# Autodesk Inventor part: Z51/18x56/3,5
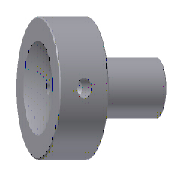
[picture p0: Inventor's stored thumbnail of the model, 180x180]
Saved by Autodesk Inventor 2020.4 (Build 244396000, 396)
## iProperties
Created: 2019-01
Part Number: Z51/18x56/3,5
Material: 1.2826
Description: Buse d'injection
Document SubType Name: Modeling
Designer: mel
Standard Revision: 1
Manufacturer: HASCO
Language: fr-FR
Size Designation: 18x56/3,5
Categories: <MemberInstance><Categories><Category DisplayName="Moule" InternalName="349578f2-f4d4-4954-8c09-8e99297a61c0" Mnemonic="MOLD"><Category DisplayName="Canal d'inj
Density: 7.82 g/cm^3
Appearance: Par défaut
Mass: 449.949 g
Surface Area: 98.7904 cm^2
Volume: 57.5383 cm^3
IsCustomPart: 1
Author: mel
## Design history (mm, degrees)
workplane "Work Plane1"
sketch "Sketch4"
  geometry: L1 (0, -98.4)-(0, 58.4) reference; L2 (0, 36)-(19.5, 36); L3 (19.5, 36)-(19.5, 0); L4 (9, -56)-(0, -56); L5 (0, -56)-(0, 36); L6 (9, -3)-(9, -56); L7 (12, 0)-(19.5, 0); L8 (12, 0)-(9, -3); 2 further points
  constraints: 14 end point, 4 point on line, 2 horizontal, 2 parallel, 1 perpendicular, 1 vertical
  dimensions: "d56" = 3 distance of L7.start point (9, 0) (= R3_CS); "d57" = 3 distance of L6.start point (9, 0) (= d56); "d58" = 39 diameter of L3 L1 (= d1_CS); "d59" = 36 distance between parallel lines of L7 L2 (= K_CS); "d60" = 18 diameter of L6 L1 (= D_CS); "d61" = 56 distance between parallel lines of L7 L4 (= L_CS)
feature "RévolutionSrf1" sketch "Sketch4" dims angle "d33" = 90 deg
feature "Sculpter4"
body "Solid1"
revolve "Révolution1" stored, may be unused: angle "d10" = 90 deg
revolve "Révolution2" stored, may be unused: angle "d13" = 90 deg
sketch "Sketch3"
  geometry: 2 further points
  constraints: 1 vertical alignment
  dimensions: "d43" = 9 distance of point (0, -9) point (0, 0) (= 0.5 x K_)
hole "Perçage1" sketch "Sketch3" diameter "d15" = 4 (= pd1); stored, may be unused: countersink angle "d19" = 90 deg, drill point angle "d21" = 118 deg; dims "d16" = 6, "d17" = 4, "d18" = 2, "d20" = 6 (= pl1)
chamfer "Chanfrein1" distance "d22" = 0.3; stored, may be unused: second distance "d23" = 2, angle "d24" = 45 deg
sketch "Sketch1"
  geometry: L1 (0, -94.8)-(0, 36.8) reference; L2 (1.75, 18)-(19, 18); L3 (19, 18)-(19, 0); L4 (19, 0)-(12, 0); L5 (9, -3)-(9, -56); L6 (9, -56)-(3.688, -56); L7 (3.688, -56)-(1.75, 18); A1 r 3 centre (12, -3) between (12, 0) and (9, -3); 2 further points
  constraints: 12 end point, 3 parallel, 2 perpendicular, 2 point on circle, 2 point on line, 2 tangent, 1 centre point
  dimensions: "d0" = 18 diameter of L5 L1 (= D); "d3" = 38 diameter of L3 L1 (= d1); "d6" = 1.5 deg angle of L7 L1 (= 0.5 x Taper); "d7" = 18 distance between parallel lines of L4 L2 (= K_); "d8" = 56 distance between parallel lines of L4 L6 (= L); "d9" = 3 radius of A1 (= R3); "d62" = 3.5 diameter of point (1.75, 18) L1 (= d_); "d63" = 0 distance from line of point (1.75, 18) L2 (computed from Rd)
sketch "Sketch2"
  geometry: L1 (0, -100.98)-(0, 73.881) reference; L2 (3.688, -56)-(1.75, 18) reference; L3 (-19, 18)-(19, 18) reference; L4 (0, 48.901)-(0, 17.901); A1 r 15.5 centre (0, 33.401) between (0, 17.901) and (0, 48.901); 2 further points
  constraints: 3 point on circle, 3 point on line, 2 end point, 1 centre point, 1 midpoint
  dimensions: "d64" = 0 distance from line of point (1.75, 18) L3 (computed from Rd); "d67" = 15.5 radius of A1 (= Rk)
body "Srf1"
feature "Surface2"
body "Srf3"
other parameters: "L" = 56 [user parameter; used in 1 equation term], "d1" = 38 [user parameter; used in 1 equation term], "d_" = 3.5 [user parameter; used in 1 equation term], "D" = 18 [user parameter; used in 1 equation term], "K_" = 18 [user parameter; used in 2 equation terms], "R" = 0 [user parameter], "Taper" = 3 deg [user parameter; used in 1 equation term], "Rd" = 0 [user parameter; used in 2 equation terms], "R3" = 3 [user parameter; used in 1 equation term], "pd1" = 4 [user parameter; used in 1 equation term], "d1_CS" = 39 [user parameter; used in 1 equation term], "K_CS" = 36 [user parameter; used in 1 equation term], "d44" = 0, "d45" = 0, "d46" = 0, "L_CS" = 56 [user parameter; used in 1 equation term], "D_CS" = 18 [user parameter; used in 1 equation term], "pl1" = 6 [user parameter; used in 1 equation term], "R3_CS" = 3 [user parameter; used in 1 equation term], "Rk" = 15.5 [user parameter; used in 1 equation term]
